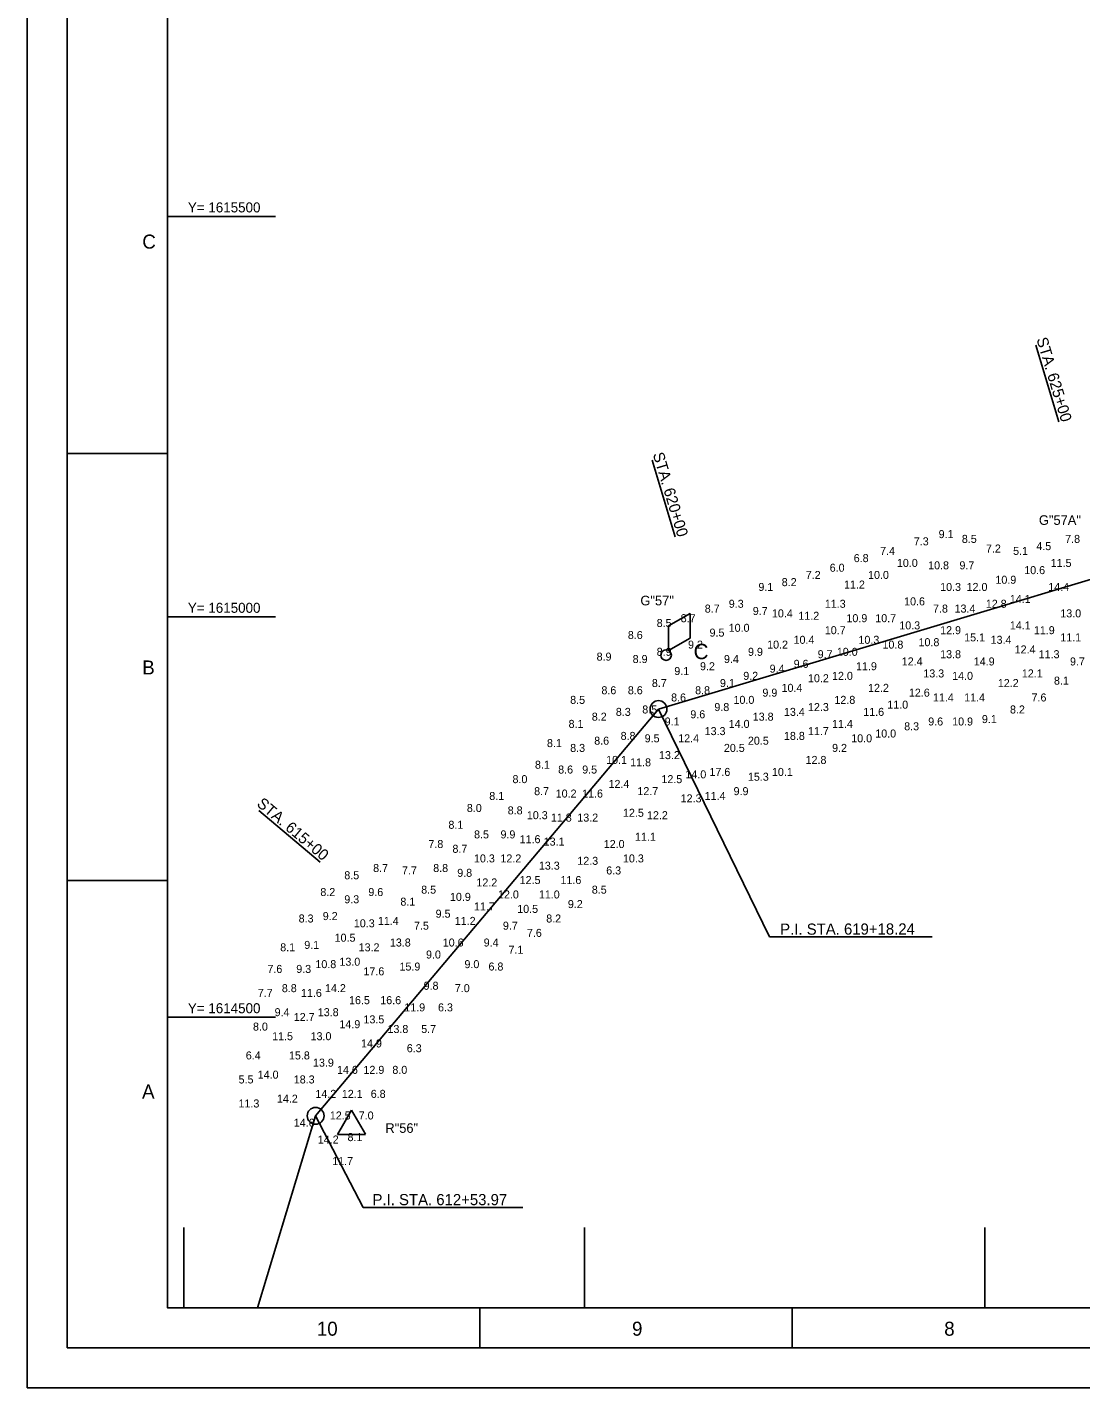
# Model space of a CAD drawing. Extents: x 442804 to 447204, y 1614037 to 1617437.
# Drawn here: x 442804 to 444120, y 1614037 to 1615736 of the extents above; entities that cross this region are included whole.
import ezdxf

# ---------------------------------------------------------------- set-up
doc = ezdxf.new("R2010")
doc.units = 0
for name, color, linetype in [('Default', 7, 'Continuous'), ('G-ANNO-NPLT', 7, 'Continuous'), ('G-ANNO-TTLB', 7, 'Continuous'), ('V-ALGN-TEXT', 7, 'Continuous'), ('V-CHAN-CNTR', 7, 'Continuous'), ('V-CHAN-CNTR-IDEN', 7, 'Continuous'), ('V-CHAN-NAID', 7, 'Continuous'), ('V-TOPO-COOR-STAT', 7, 'Continuous')]:
    doc.layers.add(name, color=color, linetype=linetype)

msp = doc.modelspace()

# ---------------------------------------------------------------- linework, layer by layer
at = {"layer": 'G-ANNO-NPLT'}
msp.add_lwpolyline([(442804.3, 1617437.2), (447204.3, 1617437.2), (447204.3, 1614037.3), (442804.3, 1614037.3)], close=True, dxfattribs=at)
msp.add_lwpolyline([(442804.3, 1614087.3), (442804.3, 1614037.3), (442854.3, 1614037.3)], dxfattribs=at)
at = {"layer": 'G-ANNO-TTLB'}
for p, q in [((442854.3, 1615203.9), (442979.3, 1615203.9)), ((442854.3, 1614670.6), (442979.3, 1614670.6)), ((443369.3, 1614087.3), (443369.3, 1614137.3)), ((443759.3, 1614087.3), (443759.3, 1614137.3))]:
    msp.add_line(p, q, dxfattribs=at)
for points in [[(442854.3, 1614087.3), (447154.3, 1614087.3), (447154.3, 1617387.2), (442854.3, 1617387.2)], [(447104.3, 1617337.2), (442979.3, 1617337.2), (442979.3, 1614137.3), (447104.3, 1614137.3)]]:
    msp.add_lwpolyline(points, close=True, dxfattribs=at)
at = {"layer": 'V-ALGN-TEXT'}
for p, q in [((444063.5, 1615339.2), (444092.2, 1615243.4)), ((443584.6, 1615195.6), (443613.3, 1615099.8)), ((443592.4, 1614884.8), (443730.9, 1614600.2)), ((443093.5, 1614758.2), (443170, 1614693.8)), ((443730.9, 1614600.2), (443934.2, 1614600.5)), ((443164.4, 1614376.8), (443223.6, 1614262.5)), ((443423.2, 1614262.5), (443223.6, 1614262.5))]:
    msp.add_line(p, q, dxfattribs=at)
at = {"layer": 'V-CHAN-CNTR'}
for p, q in [((443592.4, 1614884.8), (444169.4, 1615057.8)), ((443164.4, 1614376.8), (443592.4, 1614884.8)), ((443092, 1614137.3), (443164.4, 1614376.8))]:
    msp.add_line(p, q, dxfattribs=at)
at = {"layer": 'V-CHAN-CNTR-IDEN'}
for centre in [(443592.4, 1614884.8), (443164.4, 1614376.8)]:
    msp.add_circle(centre, 10.5, dxfattribs=at)
at = {"layer": 'V-CHAN-NAID'}
for p, q in [((443605, 1614988.8), (443631.8, 1615004.3)), ((443631.8, 1615004.3), (443631.8, 1614973.4)), ((443605, 1614958), (443605, 1614988.8)), ((443631.8, 1614973.4), (443605, 1614958)), ((443191.6, 1614353.7), (443209.2, 1614384.1)), ((443209.2, 1614384.1), (443226.6, 1614353.9)), ((443226.7, 1614353.7), (443191.6, 1614353.7))]:
    msp.add_line(p, q, dxfattribs=at)
msp.add_circle((443601.9, 1614952.2), 6.6, dxfattribs=at)
at = {"layer": 'V-TOPO-COOR-STAT'}
for p, q in [((442979.3, 1615500), (443114.3, 1615500)), ((442979.3, 1615000), (443114.3, 1615000)), ((442979.3, 1614500), (443114.3, 1614500)), ((443000, 1614137.3), (443000, 1614237.3)), ((443500, 1614137.3), (443500, 1614237.3)), ((444000, 1614137.3), (444000, 1614237.3))]:
    msp.add_line(p, q, dxfattribs=at)

# ---------------------------------------------------------------- texts
at = {"layer": 'Default'}
for s, p in [('9.1', (443942.2, 1615098.3)), ('7.4', (443869.2, 1615077.3)), ('7.3', (443911.2, 1615089.3)), ('8.5', (443971.2, 1615092.3)), ('7.2', (444001.3, 1615080.3)), ('5.1', (444035.2, 1615077.3)), ('4.5', (444064.2, 1615083.3)), ('7.8', (444100.2, 1615092.3)), ('6.8', (443836.2, 1615068.3)), ('10.0 ', (443890.1, 1615062.3)), ('11.5 ', (444082.1, 1615062.3)), ('7.2', (443776.3, 1615047.3)), ('6.0', (443806.2, 1615056.3)), ('10.0 ', (443854.1, 1615047.3)), ('10.8 ', (443929.1, 1615059.3)), ('9.7', (443968.2, 1615059.3)), ('10.6 ', (444049.1, 1615053.3)), ('9.1', (443717.2, 1615032.3)), ('8.2', (443746.3, 1615038.3)), ('11.2 ', (443824.1, 1615035.3)), ('10.3 ', (443944.1, 1615032.3)), ('12.0 ', (443977.1, 1615032.3)), ('10.9 ', (444013.1, 1615041.3)), ('14.4 ', (444079.1, 1615032.3)), ('9.3', (443680.2, 1615011.3)), ('11.3 ', (443800.1, 1615011.3)), ('10.6 ', (443899.1, 1615014.3)), ('12.8 ', (444001.1, 1615011.3)), ('14.1 ', (444031.1, 1615017.3)), ('8.7', (443620.2, 1614993.3)), ('8.7', (443650.2, 1615005.3)), ('9.7', (443710.2, 1615002.3)), ('10.4 ', (443734.1, 1614999.3)), ('11.2 ', (443767.1, 1614996.3)), ('10.9 ', (443827.1, 1614993.3)), ('10.7 ', (443863.1, 1614993.3)), ('7.8', (443935.2, 1615005.3)), ('13.4 ', (443962.1, 1615005.3)), ('13.0 ', (444094.1, 1614999.3)), ('8.5', (443590.2, 1614987.3)), ('9.5', (443656.2, 1614975.3)), ('10.0 ', (443680.1, 1614981.3)), ('10.7 ', (443800.1, 1614978.3)), ('10.3 ', (443893.1, 1614984.3)), ('12.9 ', (443944.1, 1614978.3)), ('14.1 ', (444031.1, 1614984.3)), ('11.9 ', (444061.1, 1614978.3)), ('8.6', (443554.2, 1614972.3)), ('9.2', (443629.3, 1614960.3)), ('10.2 ', (443728.1, 1614960.3)), ('10.4 ', (443761.1, 1614966.3)), ('10.3 ', (443842.1, 1614966.3)), ('10.8 ', (443872.1, 1614960.3)), ('10.8 ', (443917.1, 1614963.3)), ('15.1 ', (443974.1, 1614969.3)), ('13.4 ', (444007.1, 1614966.3)), ('11.1 ', (444094.1, 1614969.3)), ('8.9', (443515.2, 1614945.3)), ('8.9', (443560.2, 1614942.3)), ('8.9', (443590.2, 1614951.3)), ('9.4', (443674.2, 1614942.3)), ('9.9', (443704.2, 1614951.3)), ('9.7', (443791.2, 1614948.3)), ('10.0 ', (443815.1, 1614951.3)), ('13.8 ', (443944.1, 1614948.3)), ('12.4 ', (444037.1, 1614954.3)), ('11.3 ', (444067.1, 1614948.3)), ('9.1', (443612.2, 1614927.3)), ('9.2', (443644.3, 1614933.3)), ('9.4', (443731.2, 1614930.3)), ('9.6', (443761.2, 1614936.3)), ('11.9 ', (443839.1, 1614933.3)), ('12.4 ', (443896.1, 1614939.3)), ('13.3 ', (443923.1, 1614924.3)), ('14.9 ', (443986.1, 1614939.3)), ('12.1 ', (444046.1, 1614924.3)), ('9.7', (444106.2, 1614939.3)), ('8.7', (443584.2, 1614912.3)), ('9.1', (443669.2, 1614912.3)), ('9.2', (443698.3, 1614921.3)), ('10.2 ', (443779.1, 1614918.3)), ('12.0 ', (443809.1, 1614921.3)), ('14.0 ', (443959.1, 1614921.3)), ('12.2 ', (444016.1, 1614912.3)), ('8.1', (444086.2, 1614915.3)), ('8.5', (443482.2, 1614891.3)), ('8.6', (443521.2, 1614903.3)), ('8.6', (443554.2, 1614903.3)), ('8.6', (443608.2, 1614894.3)), ('8.8', (443638.2, 1614903.3)), ('10.0 ', (443686.1, 1614891.3)), ('9.9', (443722.2, 1614900.3)), ('10.4 ', (443746.1, 1614906.3)), ('12.8 ', (443812.1, 1614891.3)), ('12.2 ', (443854.1, 1614906.3)), ('12.6 ', (443905.1, 1614900.3)), ('11.4 ', (443935.1, 1614894.3)), ('11.4 ', (443974.1, 1614894.3)), ('7.6', (444058.2, 1614894.3)), ('8.3', (443539.2, 1614876.3)), ('8.5', (443572.2, 1614879.3)), ('9.6', (443632.2, 1614873.3)), ('9.8', (443662.2, 1614882.3)), ('13.4 ', (443749.1, 1614876.3)), ('12.3 ', (443779.1, 1614882.3)), ('11.6 ', (443848.1, 1614876.3)), ('11.0 ', (443878.1, 1614885.3)), ('8.2', (444031.3, 1614879.3)), ('8.1', (443480.2, 1614861.3)), ('8.2', (443509.2, 1614870.3)), ('9.1', (443600.2, 1614864.3)), ('14.0 ', (443680.1, 1614861.3)), ('13.8 ', (443710.1, 1614870.3)), ('11.4 ', (443809.1, 1614861.3)), ('8.3', (443899.2, 1614858.3)), ('9.6', (443929.2, 1614864.3)), ('10.9 ', (443959.1, 1614864.3)), ('9.1', (443996.2, 1614867.3)), ('8.6', (443512.2, 1614840.3)), ('8.8', (443545.2, 1614846.3)), ('9.5', (443575.2, 1614843.3)), ('12.4 ', (443617.1, 1614843.3)), ('13.3 ', (443650.1, 1614852.3)), ('20.5 ', (443704.1, 1614840.3)), ('18.8 ', (443749.1, 1614846.3)), ('11.7 ', (443779.1, 1614852.3)), ('10.0 ', (443833.1, 1614843.3)), ('10.0 ', (443863.1, 1614849.3)), ('8.1', (443453.2, 1614837.3)), ('8.3', (443482.2, 1614831.3)), ('13.2 ', (443593.1, 1614822.3)), ('20.5 ', (443674.1, 1614831.3)), ('9.2', (443809.2, 1614831.3)), ('8.1', (443438.2, 1614810.3)), ('10.1 ', (443527.1, 1614816.3)), ('11.8 ', (443557.1, 1614813.3)), ('12.8 ', (443776.1, 1614816.3)), ('8.0', (443410.2, 1614792.3)), ('8.6', (443467.2, 1614804.3)), ('9.5', (443497.2, 1614804.3)), ('12.5 ', (443596.1, 1614792.3)), ('14.0 ', (443626.1, 1614798.3)), ('17.6 ', (443656.1, 1614801.3)), ('15.3 ', (443704.1, 1614795.3)), ('10.1 ', (443734.1, 1614801.3)), ('8.1', (443381.2, 1614771.3)), ('8.7', (443437.2, 1614777.3)), ('10.2 ', (443464.1, 1614774.3)), ('11.6 ', (443497.1, 1614774.3)), ('12.4 ', (443530.1, 1614786.3)), ('12.7 ', (443566.1, 1614777.3)), ('9.9', (443686.2, 1614777.3)), ('8.0', (443353.2, 1614756.3)), ('12.3 ', (443620.1, 1614768.3)), ('11.4 ', (443650.1, 1614771.3)), ('8.8', (443404.2, 1614753.3)), ('10.3 ', (443428.1, 1614747.3)), ('11.8 ', (443458.1, 1614744.3)), ('13.2 ', (443491.1, 1614744.3)), ('12.5 ', (443548.1, 1614750.3)), ('12.2 ', (443578.1, 1614747.3)), ('8.1', (443330.2, 1614735.3)), ('8.5', (443362.2, 1614723.3)), ('9.9', (443395.2, 1614723.3)), ('7.8', (443305.2, 1614711.3)), ('8.7', (443335.2, 1614705.3)), ('11.6 ', (443419.1, 1614717.3)), ('13.1 ', (443449.1, 1614714.3)), ('12.0 ', (443524.1, 1614711.3)), ('11.1 ', (443563.1, 1614720.3)), ('10.3 ', (443362.1, 1614693.3)), ('12.2 ', (443395.1, 1614693.3)), ('12.3 ', (443491.1, 1614690.3)), ('10.3 ', (443548.1, 1614693.3)), ('8.5', (443200.2, 1614672.3)), ('8.7', (443236.2, 1614681.3)), ('7.7', (443272.2, 1614678.3)), ('8.8', (443311.2, 1614681.3)), ('9.8', (443341.2, 1614675.3)), ('13.3 ', (443443.1, 1614684.3)), ('6.3', (443527.2, 1614678.3)), ('8.5', (443296.2, 1614654.3)), ('12.2 ', (443365.1, 1614663.3)), ('12.5 ', (443419.1, 1614666.3)), ('11.6 ', (443470.1, 1614666.3)), ('8.5', (443509.2, 1614654.3)), ('8.2', (443170.3, 1614651.3)), ('9.3', (443200.2, 1614642.3)), ('9.6', (443230.2, 1614651.3)), ('8.1', (443270.2, 1614639.3)), ('10.9 ', (443332.1, 1614645.3)), ('12.0 ', (443392.1, 1614648.3)), ('11.0 ', (443443.1, 1614648.3)), ('9.2', (443479.3, 1614636.3)), ('9.2', (443173.3, 1614621.3)), ('9.5', (443314.2, 1614624.3)), ('11.7 ', (443362.1, 1614633.3)), ('10.5 ', (443416.1, 1614630.3)), ('8.3', (443143.2, 1614618.3)), ('10.3 ', (443212.1, 1614612.3)), ('11.4 ', (443242.1, 1614615.3)), ('7.5', (443287.2, 1614609.3)), ('11.2 ', (443338.1, 1614615.3)), ('9.7', (443398.2, 1614609.3)), ('8.2', (443452.3, 1614618.3)), ('9.1', (443150.2, 1614585.3)), ('10.5 ', (443188.1, 1614594.3)), ('13.8 ', (443257.1, 1614588.3)), ('10.6 ', (443323.1, 1614588.3)), ('9.4', (443374.2, 1614588.3)), ('7.6', (443428.2, 1614600.3)), ('8.1', (443120.2, 1614582.3)), ('13.2 ', (443218.1, 1614582.3)), ('9.0', (443302.2, 1614573.3)), ('7.1', (443405.2, 1614579.3)), ('7.6', (443104.2, 1614555.3)), ('9.3', (443140.2, 1614555.3)), ('10.8 ', (443164.1, 1614561.3)), ('13.0 ', (443194.1, 1614564.3)), ('17.6 ', (443224.1, 1614552.3)), ('15.9 ', (443269.1, 1614558.3)), ('9.0', (443350.2, 1614561.3)), ('6.8', (443380.2, 1614558.3)), ('9.8', (443299.2, 1614534.3)), ('7.7', (443092.2, 1614525.3)), ('8.8', (443122.2, 1614531.3)), ('11.6 ', (443146.1, 1614525.3)), ('14.2 ', (443176.1, 1614531.3)), ('7.0', (443338.2, 1614531.3)), ('9.4', (443113.2, 1614501.3)), ('13.8 ', (443167.1, 1614501.3)), ('16.5 ', (443206.1, 1614516.3)), ('16.6 ', (443245.1, 1614516.3)), ('11.9 ', (443275.1, 1614507.3)), ('6.3', (443317.2, 1614507.3)), ('8.0', (443086.2, 1614483.3)), ('12.7 ', (443137.1, 1614495.3)), ('14.9 ', (443194.1, 1614486.3)), ('13.5 ', (443224.1, 1614492.3)), ('11.5 ', (443110.1, 1614471.3)), ('13.0 ', (443158.1, 1614471.3)), ('13.8 ', (443254.1, 1614480.3)), ('5.7', (443296.2, 1614480.3)), ('14.9 ', (443221.1, 1614462.3)), ('6.3', (443278.2, 1614456.3)), ('6.4', (443077.2, 1614447.3)), ('15.8 ', (443131.1, 1614447.3)), ('13.9 ', (443161.1, 1614438.3)), ('5.5', (443068.2, 1614417.3)), ('14.0 ', (443092.1, 1614423.3)), ('18.3 ', (443137.1, 1614417.3)), ('14.6 ', (443191.1, 1614429.3)), ('12.9 ', (443224.1, 1614429.3)), ('8.0', (443260.2, 1614429.3)), ('14.2 ', (443164.1, 1614399.3)), ('12.1 ', (443197.1, 1614399.3)), ('6.8', (443233.2, 1614399.3)), ('11.3 ', (443068.1, 1614387.3)), ('14.2 ', (443116.1, 1614393.3)), ('12.5 ', (443182.1, 1614372.3)), ('7.0', (443218.2, 1614372.3)), ('14.6 ', (443137.1, 1614363.3)), ('14.2 ', (443167.1, 1614342.3)), ('8.1', (443204.2, 1614345.3)), ('11.7 ', (443185.1, 1614315.3))]:
    msp.add_text(s, height=10, dxfattribs=at).set_placement(p)
at = {"layer": 'G-ANNO-TTLB'}
for s, p in [('C', (442948, 1615459.8)), ('B', (442947.9, 1614928)), ('A', (442947.7, 1614398.5)), ('10', (443165.9, 1614102.3)), ('9', (443559.4, 1614102.3)), ('8', (443949.2, 1614102.3))]:
    msp.add_text(s, height=17.5, dxfattribs=at).set_placement(p)
at = {"layer": 'V-ALGN-TEXT'}
for s, rotation, p in [('STA. 625+00', 286.6896, (444064.2, 1615346.8)), ('STA. 620+00', 286.6896, (443585.2, 1615203.2)), ('STA. 615+00', 319.8853, (443089.9, 1614764.9)), ('P.I. STA. 619+18.24', 0.0976, (443744.4, 1614603))]:
    msp.add_text(s, height=13.92, rotation=rotation, dxfattribs=at).set_placement(p)
msp.add_text('P.I. STA. 612+53.97', height=13.92, dxfattribs=at).set_placement((443235.4, 1614265.3))
at = {"layer": 'V-CHAN-NAID'}
for s, p in [('G"57A"', (444067.4, 1615114.8)), ('G"57"', (443569.9, 1615014.3)), ('R"56"', (443251.5, 1614355.6))]:
    msp.add_text(s, height=12, dxfattribs=at).set_placement(p)
msp.add_text('C', height=19.2, rotation=0.0027, dxfattribs=at).set_placement((443636.3, 1614947.1))
at = {"layer": 'V-TOPO-COOR-STAT'}
for s, p in [('Y= 1615500', (443004.9, 1615505)), ('Y= 1615000', (443004.9, 1615005)), ('Y= 1614500', (443004.9, 1614505))]:
    msp.add_text(s, height=12.5, dxfattribs=at).set_placement(p)

doc.saveas('drawing.dxf')
